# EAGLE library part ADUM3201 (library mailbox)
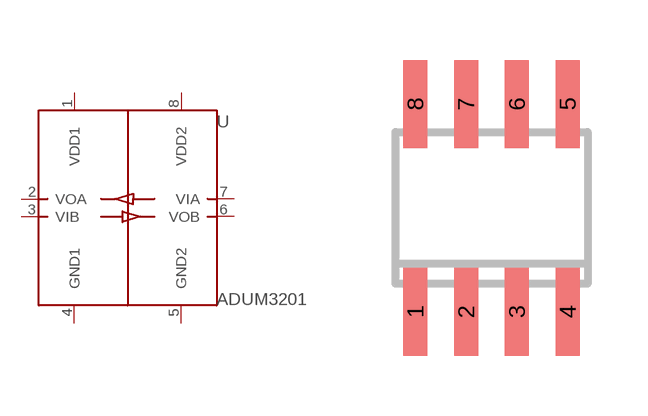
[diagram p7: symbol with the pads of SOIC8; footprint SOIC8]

Designator prefix -

## ADUM3201  [SOIC8]
1  VDD1  pwr
2  VOA  out
3  VIB  in
4  GND1  pwr
5  GND2  pwr
6  VOB  out
7  VIA  in
8  VDD2  pwr

## Footprint SOIC8 (pad centres in mm)
Small Outline IC
smd 0.6 x 2.2: 1 -1.905,-2.6; 2 -0.635,-2.6; 3 0.635,-2.6; 4 1.905,-2.6; 5 1.905,2.6; 6 0.635,2.6; 7 -0.635,2.6; 8 -1.905,2.6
